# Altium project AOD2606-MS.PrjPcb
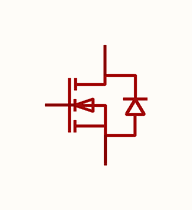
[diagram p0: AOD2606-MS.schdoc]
1 sheet, 1 parts. Net scope: global (net labels, ports and power ports of the same name join across sheets).

## Sheet AOD2606-MS.schdoc
size 127 x 101 mm

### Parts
Q?  aod2606-ms  [TO-252-3_L6.6-W6.1-P4.57-LS9.9-BR-CW]  (value not drawn)

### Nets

Not connected (* = marked no-connect by the designer): Q? 1(G) 2(D) 3(S)

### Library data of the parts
Q? = aod2606-ms: 数量:1个N沟道;漏源电压(Vdss):60V;连续漏极电流(Id):80A;导通电阻(RDS(on)):6mΩ@10V;耗散功率(Pd):104W;阈值电压(Vgs(th)):1.4V;; Manufacturer: MSKSEMI(美森科); AddInBom: yes; ModelId: dee852f3c6b348a2b9d5be5dd3244081; ModelTransform: 258.97184,390.1567,0,90,0,0,-35.433,0,0; Number: 1个N沟道; Drain to Source Voltage: 60V; Current - Continuous Drain(Id): 80A; Pd - Power Dissipation: 104W; Gate Threshold Voltage (Vgs(th)): 1.4V; Gate Charge(Qg): 33nC; Input Capacitance(Ciss): 2.68nF; Reverse Transfer Capacitance (Crss@Vds): 180pF; Type: N沟道; Output Capacitance(Coss): 260pF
